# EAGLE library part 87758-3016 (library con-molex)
30 Pin - 2mm Dual Row Single Wafer, Vertical T/H HDR Source: http://www.molex.com/pdm_docs/sd/877580616_sd.pdf
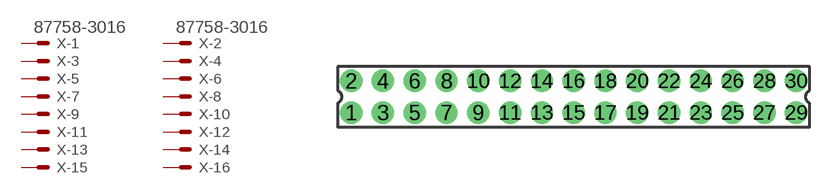
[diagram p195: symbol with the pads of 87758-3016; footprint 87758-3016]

Designator prefix X; gates -1=MV -2=MV -3=M -4=M -5=M -6=M -7=M -8=M -9=M -10=M -11=M -12=M -13=M -14=M -15=M -16=M -17=M -18=M -19=M -20=M -21=M -22=M -23=M -24=M -25=M -26=M -27=M -28=M -29=M -30=M

## 87758-3016 (MF: MOLEX; MPN: 87758-3016; OC_FARNELL: unknown; OC_NEWARK: 59J1575)  [87758-3016]
1  -1:S  pas
2  -2:S  pas
3  -3:S  pas
4  -4:S  pas
5  -5:S  pas
6  -6:S  pas
7  -7:S  pas
8  -8:S  pas
9  -9:S  pas
10  -10:S  pas
11  -11:S  pas
12  -12:S  pas
13  -13:S  pas
14  -14:S  pas
15  -15:S  pas
16  -16:S  pas
17  -17:S  pas
18  -18:S  pas
19  -19:S  pas
20  -20:S  pas
21  -21:S  pas
22  -22:S  pas
23  -23:S  pas
24  -24:S  pas
25  -25:S  pas
26  -26:S  pas
27  -27:S  pas
28  -28:S  pas
29  -29:S  pas
30  -30:S  pas

## Footprint 87758-3016 (pad centres in mm)
30 Pin - 2mm Dual Row Single Wafer, Vertical T/H HDR Source: http://www.molex.com/pdm_docs/sd/877580616_sd.pdf
drill 0.9 pad 1.27 round: 1 -14,-1; 2 -14,1; 3 -12,-1; 4 -12,1; 5 -10,-1; 6 -10,1; 7 -8,-1; 8 -8,1; 9 -6,-1; 10 -6,1; 11 -4,-1; 12 -4,1; 13 -2,-1; 14 -2,1; 15 0,-1; 16 0,1; 17 2,-1; 18 2,1; 19 4,-1; 20 4,1; 21 6,-1; 22 6,1; 23 8,-1; 24 8,1; 25 10,-1; 26 10,1; 27 12,-1; 28 12,1; 29 14,-1; 30 14,1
